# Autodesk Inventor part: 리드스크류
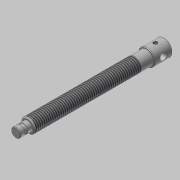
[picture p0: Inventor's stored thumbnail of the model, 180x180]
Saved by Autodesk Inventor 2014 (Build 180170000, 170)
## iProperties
Created: 2019-04
Part Number: 리드스크류
Material: 강철, 연강
Document SubType Name: Modeling
Designer: mduedu
Density: 1 g/cm^3
Appearance: Steel
Author: mduedu
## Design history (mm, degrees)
sketch "스케치1"
  geometry: C1 r 6 at (0, 0); 1 further point
  constraints: 1 centre point, 1 coincident
  dimensions: "d0" = 12 diameter of C1
extrude "돌출1" new body sketch "스케치1" distance "d1" = 100; taper "d2" = 0 deg
sketch "스케치2"
  geometry: C1 r 4 at (0, 0); 1 further point
  constraints: 1 centre point, 1 coincident
  dimensions: "d3" = 8 diameter of C1
extrude "돌출2" join sketch "스케치2" distance "d4" = 10; taper "d5" = 0 deg
sketch "스케치3"
  geometry: C1 r 7 at (0, 0); 1 further point
  constraints: 1 centre point, 1 coincident
  dimensions: "d9" = 14 diameter of C1
extrude "돌출3" join sketch "스케치3" distance "d10" = 15; taper "d11" = 0 deg
feature "스레드1" dims "d12" = 90, "d13" = 0
chamfer "모따기2" distance "d14" = 1; stored, may be unused: second distance "d15" = 2, angle "d16" = 45 deg
chamfer "모따기3" distance "d17" = 0.5; stored, may be unused: second distance "d18" = 2, angle "d19" = 45 deg
chamfer "모따기4" distance "d20" = 0.5; stored, may be unused: second distance "d21" = 2, angle "d22" = 45 deg
sketch "스케치4"
  geometry: L1 (-100, -5)-(-100, 5) reference; L2 (-109.5, 4)-(-109.5, -4) reference; L3 (-109.5, 0)-(-100, 0); C1 r 1.25 at (-105, 4); 1 further point
  constraints: 2 end point, 2 midpoint, 1 centre point
  dimensions: "d23" = 2.5 diameter of C1; "d24" = 5 distance from line of C1.centre L1; "d25" = 4 distance from line of C1.centre L3
revolve "회전1" sketch "스케치4" stored, may be unused: angle "d26" = 90 deg
sketch "스케치5"
  geometry: L1 (0, -6.5)-(0, 6.5) reference; C1 r 3 at (7.5, 0); 2 further points
  constraints: 1 centre point, 1 horizontal alignment, 1 midpoint
  dimensions: "d27" = 6 diameter of C1; "d28" = 7.5 distance from line of C1.centre L1
extrude "돌출4" cut sketch "스케치5" stored distance "d29" = 15; taper "d30" = 0 deg
node "작업 평면1"
sketch "스케치6"
  geometry: L1 (0, 6.5)-(0, -6.5) reference; 2 further points
  constraints: 1 horizontal alignment
  dimensions: "d31" = 7.5 distance from line of point (-7.5, 0) L1
hole "구멍1" sketch "스케치6" at (-7.5, 0) diameter "d32" = 3.242; stored, may be unused: countersink angle "d36" = 90 deg, drill point angle "d38" = 118 deg; dims "d33" = 6, "d34" = 4, "d35" = 2, "d37" = 8
node "솔리드1"
